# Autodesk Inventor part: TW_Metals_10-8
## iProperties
Shininess: 64.0
Length Units: 11272
Angle Units: 11279
Time Units: 11290
Mass Units: 11286
Length Display Precision: 3
Angle Display Precision: 2
Compacted: True
Part Number: TW_Metals_10-8
Document SubType Name: Modeling
Created: 2005-05
Designer: John Blackburn
Material: Aluminum-6061
Manufacturer: Standard
Standards Organization: Custom
Density: 0.0
Volumn: 0.0
Area: 0.0
PropertySet Name: Model Information
Control State: 0
Master: False
Checked Out: False
Author: John Blackburn
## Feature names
1. Extrusion1
